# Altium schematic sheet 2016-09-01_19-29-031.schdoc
size 223 x 111 mm; SheetNumber: 1; SheetTotal: 1
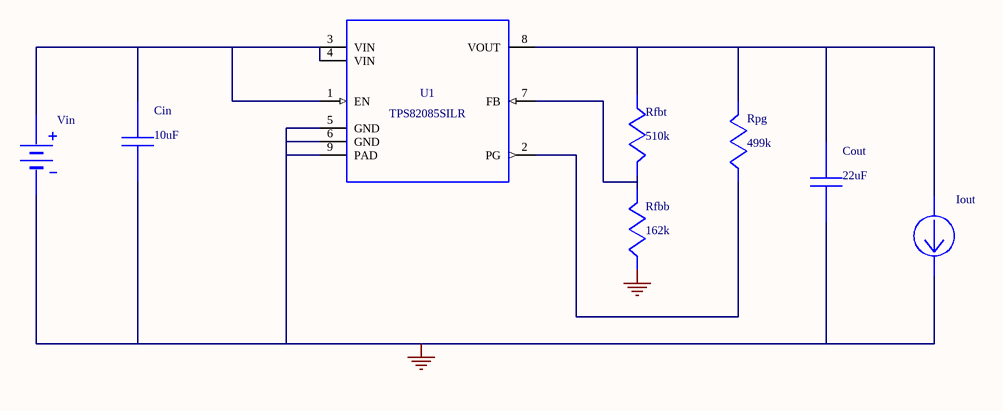
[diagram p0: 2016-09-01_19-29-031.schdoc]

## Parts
Cin  value 10uF  (hidden comment: LMK212BJ106KG-T)
Cout  value 22uF  (hidden comment: GRM32ER71C226KE18L)
Iout  WB_CURRENT_LOAD  (value not drawn)
Rfbb  value 162k  (hidden comment: CRCW0402162KFKED)
Rfbt  value 510k  (hidden comment: RC0603FR-07510KL)
Rpg  value 499k  (hidden comment: CRCW0402499KFKED)
U1  TPS82085SILR
Vin  WB_BATTERY  (value not drawn)

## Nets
0: Cin.2 Cout.2 Iout.2(-) Rfbb.2 U1.5(GND) U1.6(GND) U1.9(PAD) Vin.2(-)
NetCin_1: Cin.1 U1.1(EN) U1.3(VIN) U1.4(VIN) Vin.1(+)
NetCout_1: Cout.1 Iout.1(+) Rfbt.2 Rpg.1 U1.8(VOUT)
NetRfbb_1: Rfbb.1 Rfbt.1 U1.7(FB)
NetRpg_2: Rpg.2 U1.2(PG)

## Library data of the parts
Cin = LMK212BJ106KG-T: Manufacturer Name: Taiyo Yuden
Cout = GRM32ER71C226KE18L: GRM32ER71C226KE1; Manufacturer Name: MuRata
Rfbb = CRCW0402162KFKED: Manufacturer Name: Vishay-Dale
Rfbt = RC0603FR-07510KL: Manufacturer Name: Yageo America
Rpg = CRCW0402499KFKED: Manufacturer Name: Vishay-Dale
U1 = TPS82085SILR: Manufacturer Name: Texas Instruments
